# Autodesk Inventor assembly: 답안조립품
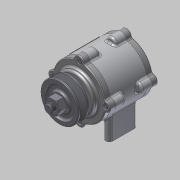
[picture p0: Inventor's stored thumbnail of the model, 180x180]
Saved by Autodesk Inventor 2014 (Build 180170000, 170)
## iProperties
Created: 2015-03
Part Number: 답안조립품
Document SubType Name: Assembly
Designer: MYHOME
Author: MYHOME
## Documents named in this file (11)
- C:\Documents and Settings\MYHOME\바탕 화면\450306V1020\답안조립품.iam
- C:\Documents and Settings\MYHOME\바탕 화면\450306V1020\본체.ipt
- C:\Documents and Settings\MYHOME\바탕 화면\450306V1020\커버.ipt
- C:\Documents and Settings\MYHOME\바탕 화면\450306V1020\커버2.ipt
- C:\Documents and Settings\MYHOME\바탕 화면\450306V1020\오일실.ipt
- C:\Documents and Settings\MYHOME\바탕 화면\450306V1020\M 4 x 12.ipt
- C:\Documents and Settings\MYHOME\바탕 화면\450306V1020\베어링 6204.ipt
- C:\Documents and Settings\MYHOME\바탕 화면\450306V1020\축.ipt
- C:\Documents and Settings\MYHOME\바탕 화면\450306V1020\키(4 x 4 x 12).ipt
- C:\Documents and Settings\MYHOME\바탕 화면\450306V1020\V벨트풀리.ipt
- C:\Documents and Settings\MYHOME\바탕 화면\450306V1020\너트 M12x1.25.ipt
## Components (14 placed, 6 different names)
1. KS B 2804 D D - 20 32 8:1
2. KS B 2023 6204 - 20 x 47 x 14:1 — 각도:1
3. KS B 2023 6204 - 20 x 47 x 14:2 — 각도:2
4. KS B 1311 (I) 4 x 4 x 12:1
5. 그루브 풀리1:1
6. KS B 1012 클래스 1 일반 - 미터 M12x1.25:1 — 각도:5
7. KS B 1003 - 미터 M 4 x 12:1
8. KS B 1003 - 미터 M 4 x 12:2
9. KS B 1003 - 미터 M 4 x 12:3
10. KS B 1003 - 미터 M 4 x 12:4
11. KS B 1003 - 미터 M 4 x 12:5
12. KS B 1003 - 미터 M 4 x 12:6
13. KS B 1003 - 미터 M 4 x 12:7
14. KS B 1003 - 미터 M 4 x 12:8
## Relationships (3: Angle 3)
- 각도:1 [Angle]: KS B 2023 6204 - 20 x 47 x 14:1
- 각도:2 [Angle]: KS B 2023 6204 - 20 x 47 x 14:2
- 각도:5 [Angle]: KS B 1012 클래스 1 일반 - 미터 M12x1.25:1
